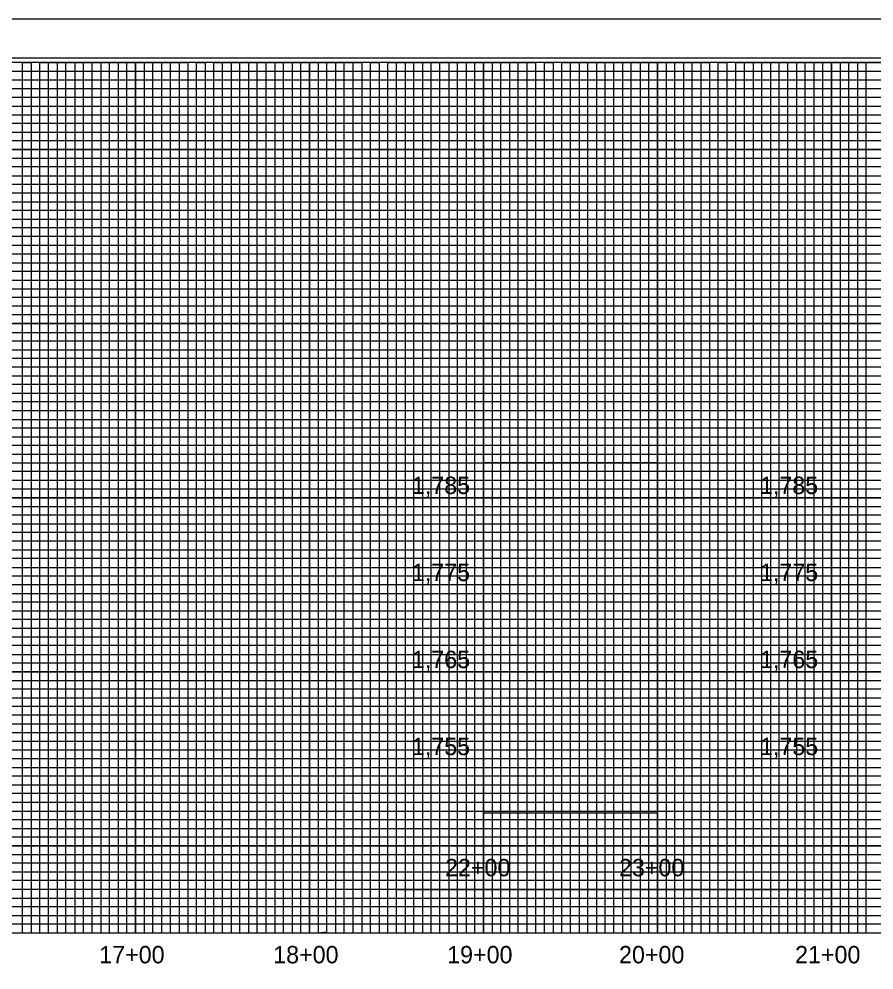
# Model space of a CAD drawing. Extents: x 505692 to 507376, y 438761 to 439861.
# Drawn here: x 506542 to 507033, y 439315 to 439861 of the extents above; entities that cross this region are included whole.
import ezdxf

# ---------------------------------------------------------------- set-up
doc = ezdxf.new("R2010")
doc.units = 0
for name, color, linetype in [('Exist Vertical Profile Vertical Axis Label', 7, 'Continuous'), ('Prop Grid Mask', 7, 'Continuous'), ('Sheet Cutting Line CELL', 7, 'Continuous'), ('Sheet DOT Grid CELL', 7, 'Continuous'), ('Sheet Layout Profile Border Port 1', 7, 'Continuous'), ('Sheet Plot Border Inside CELL', 7, 'Continuous'), ('Sheet Plot Border Outside CELL', 7, 'Continuous'), ('Sheet Profile CELL', 7, 'Continuous'), ('Sheet Profile Grid Major CELL', 7, 'Continuous'), ('Sheet Profile Grid Middle CELL', 7, 'Continuous'), ('Sheet Profile Grid Minor CELL', 7, 'Continuous')]:
    doc.layers.add(name, color=color, linetype=linetype)

msp = doc.modelspace()

# ---------------------------------------------------------------- linework, layer by layer
at = {"layer": 'Prop Grid Mask'}
msp.add_lwpolyline([(506758.68, 439386.14), (507008.68, 439386.14), (507008.68, 439361.14), (506758.68, 439361.14)], close=True, dxfattribs=at)
at = {"layer": 'Sheet Cutting Line CELL'}
msp.add_line((507375.68, 439861.14), (505691.68, 439861.14), dxfattribs=at)
at = {"layer": 'Sheet DOT Grid CELL'}
for p, q in [((506558.68, 439336.14), (506558.68, 439836.14)), ((506608.68, 439336.14), (506608.68, 439836.14)), ((506658.68, 439336.14), (506658.68, 439836.14)), ((506708.68, 439336.14), (506708.68, 439836.14)), ((506758.68, 439336.14), (506758.68, 439836.14)), ((506808.68, 439336.14), (506808.68, 439836.14)), ((506858.68, 439336.14), (506858.68, 439836.14)), ((506908.68, 439336.14), (506908.68, 439836.14)), ((506958.68, 439336.14), (506958.68, 439836.14)), ((507008.68, 439336.14), (507008.68, 439836.14)), ((507158.63, 439786.14), (505858.68, 439786.14)), ((507158.63, 439736.14), (505858.68, 439736.14)), ((507158.68, 439686.14), (505858.68, 439686.14)), ((507358.68, 439636.14), (505858.68, 439636.14)), ((507358.68, 439586.14), (505858.68, 439586.14)), ((507358.68, 439536.14), (505858.68, 439536.14)), ((507358.68, 439486.14), (505858.68, 439486.14)), ((507358.68, 439436.14), (505858.68, 439436.14)), ((507358.68, 439386.14), (505858.68, 439386.14))]:
    msp.add_line(p, q, dxfattribs=at)
at = {"layer": 'Sheet Layout Profile Border Port 1'}
for points in [[(505908.68, 439836.14), (505908.68, 439336.14), (507108.68, 439336.14), (507108.68, 439486.14), (507108.68, 439636.14), (507108.68, 439836.14)], [(506808.68, 439405.04), (506908.68, 439405.04), (506908.68, 439606.14), (506808.68, 439606.14)]]:
    msp.add_lwpolyline(points, close=True, dxfattribs=at)
at = {"layer": 'Sheet Plot Border Inside CELL'}
msp.add_lwpolyline([(505704.68, 438783.59), (507371.18, 438783.59), (507371.18, 439838.69), (505704.68, 439838.69)], close=True, dxfattribs=at)
at = {"layer": 'Sheet Plot Border Outside CELL'}
msp.add_lwpolyline([(505691.68, 438761.14), (507375.68, 438761.14), (507375.68, 439861.14), (505691.68, 439861.14)], close=True, dxfattribs=at)
at = {"layer": 'Sheet Profile CELL'}
for p, q in [((506758.68, 439361.14), (506758.68, 439611.14)), ((506758.68, 439611.14), (507008.68, 439611.14)), ((506808.68, 439386.14), (506808.68, 439611.14)), ((506958.68, 439386.14), (506958.68, 439611.14)), ((507008.68, 439361.14), (507008.68, 439611.14)), ((506758.68, 439386.14), (507008.68, 439386.14)), ((506758.68, 439361.14), (507008.68, 439361.14)), ((505858.68, 439336.14), (507358.68, 439336.14))]:
    msp.add_line(p, q, dxfattribs=at)
msp.add_lwpolyline([(507358.68, 439836.14), (505858.68, 439836.14), (505858.68, 438786.14), (507358.68, 438786.14)], close=True, dxfattribs=at)
at = {"layer": 'Sheet Profile Grid Major CELL'}
for points in [[(506508.68, 439336.14), (506558.68, 439336.14), (506558.68, 439836.14), (506608.68, 439836.14), (506608.68, 439336.14), (506658.68, 439336.14), (506658.68, 439836.14), (506708.68, 439836.14), (506708.68, 439336.14), (506758.68, 439336.14), (506758.68, 439836.14), (506808.68, 439836.14), (506808.68, 439336.14), (506858.68, 439336.14), (506858.68, 439836.14), (506908.68, 439836.14), (506908.68, 439336.14), (506958.68, 439336.14), (506958.68, 439836.14), (507008.68, 439836.14), (507008.68, 439336.14), (507058.68, 439336.14)], [(505858.68, 439786.14), (507158.68, 439786.14)], [(507158.68, 439736.14), (505858.68, 439736.14), (505858.68, 439686.14), (507158.68, 439686.14)], [(507358.68, 439636.14), (505858.68, 439636.14), (505858.68, 439586.14), (507358.68, 439586.14)], [(507358.68, 439536.14), (505858.68, 439536.14), (505858.68, 439486.14), (507358.68, 439486.14)], [(507358.68, 439436.14), (505858.68, 439436.14), (505858.68, 439436.14), (505858.68, 439386.14), (507358.68, 439386.14)]]:
    msp.add_lwpolyline(points, dxfattribs=at)
at = {"layer": 'Sheet Profile Grid Middle CELL'}
msp.add_line((505858.68, 439811.14), (507158.63, 439811.14), dxfattribs=at)
for points in [[(506533.68, 439336.14), (506583.68, 439336.14), (506583.68, 439836.14), (506633.68, 439836.14), (506633.68, 439336.14), (506683.68, 439336.14), (506683.68, 439836.14), (506733.68, 439836.14), (506733.68, 439336.14), (506783.68, 439336.14), (506783.68, 439836.14), (506833.68, 439836.14), (506833.68, 439336.14), (506883.68, 439336.14), (506883.68, 439836.14), (506933.68, 439836.14), (506933.68, 439336.14), (506983.68, 439336.14), (506983.68, 439836.14), (507033.68, 439836.14)], [(507158.68, 439761.14), (505858.68, 439761.14), (505858.68, 439711.14), (507158.68, 439711.14)], [(507358.68, 439661.14), (505858.68, 439661.14), (505858.68, 439611.14), (507183.68, 439611.14)], [(507358.68, 439561.14), (505858.68, 439561.14), (505858.68, 439511.14), (507358.68, 439511.14)], [(507358.68, 439461.14), (505858.68, 439461.14), (505858.68, 439411.14), (507358.68, 439411.14)], [(507358.68, 439361.14), (505858.68, 439361.14)]]:
    msp.add_lwpolyline(points, dxfattribs=at)
at = {"layer": 'Sheet Profile Grid Minor CELL'}
for p, q in [((505908.68, 439831.14), (507158.68, 439831.14)), ((507158.68, 439826.14), (505908.68, 439825.79)), ((505908.68, 439821.14), (507158.68, 439821.14)), ((507158.63, 439701.14), (505908.68, 439701.14)), ((507158.68, 439696.14), (505908.68, 439696.14)), ((507158.68, 439691.14), (505908.68, 439691.14)), ((505908.68, 439681.14), (507158.68, 439681.14)), ((507158.68, 439676.14), (505908.68, 439676.14)), ((505908.68, 439671.14), (507308.68, 439671.14)), ((507308.68, 439651.14), (505908.68, 439651.14)), ((505908.68, 439646.14), (507308.68, 439646.14)), ((507308.68, 439626.14), (505908.68, 439626.14)), ((505908.68, 439621.14), (507308.68, 439621.14)), ((507308.68, 439601.14), (505908.68, 439601.14)), ((505908.68, 439596.14), (507308.68, 439596.14)), ((507308.68, 439591.14), (505908.68, 439591.14)), ((505908.68, 439581.14), (507308.68, 439581.14)), ((507308.68, 439576.14), (505908.68, 439576.14)), ((505908.68, 439571.14), (507308.68, 439571.14)), ((507308.68, 439566.14), (505908.68, 439566.14)), ((505908.68, 439556.14), (507308.68, 439556.14)), ((507308.68, 439551.14), (505908.68, 439551.14)), ((505908.68, 439546.14), (507308.68, 439546.14)), ((507308.68, 439541.14), (505908.68, 439541.14)), ((505908.68, 439531.14), (507308.68, 439531.14)), ((507308.68, 439526.14), (505908.68, 439526.14)), ((505908.68, 439521.14), (507308.68, 439521.14)), ((507308.68, 439516.14), (505908.68, 439516.14)), ((505908.68, 439506.14), (507308.68, 439506.14)), ((507308.68, 439501.14), (505908.68, 439501.14)), ((505908.68, 439496.14), (507308.68, 439496.14)), ((507308.68, 439491.14), (505908.68, 439491.14)), ((505908.68, 439481.14), (507308.68, 439481.14)), ((507308.68, 439476.14), (505908.68, 439476.14)), ((505908.68, 439471.14), (507308.68, 439471.14)), ((507308.68, 439466.14), (505908.68, 439466.14)), ((505908.68, 439456.14), (507308.68, 439456.14)), ((507308.68, 439451.14), (505908.68, 439451.14)), ((507308.68, 439446.14), (505908.68, 439446.14)), ((507308.68, 439441.14), (505908.68, 439441.14)), ((505908.68, 439431.14), (507308.68, 439431.14)), ((507308.68, 439426.14), (505908.68, 439426.14)), ((505908.68, 439421.14), (507308.68, 439421.14)), ((507308.68, 439416.14), (505908.68, 439416.14)), ((505908.68, 439406.14), (507308.68, 439406.14)), ((507308.68, 439401.14), (505908.68, 439401.14)), ((505908.68, 439396.14), (507308.68, 439396.14)), ((507308.68, 439391.14), (505908.68, 439391.14)), ((505908.68, 439381.14), (507308.68, 439381.14)), ((507308.68, 439376.14), (505908.68, 439376.14)), ((505908.68, 439371.14), (507308.68, 439371.14)), ((507308.68, 439366.14), (505908.68, 439366.14)), ((505908.68, 439356.14), (507308.68, 439356.14)), ((507308.68, 439351.14), (505908.68, 439351.14)), ((505908.68, 439346.14), (507308.68, 439346.14))]:
    msp.add_line(p, q, dxfattribs=at)
for points in [[(506538.68, 439336.14), (506543.68, 439336.14), (506543.68, 439836.14), (506548.68, 439836.14), (506548.68, 439336.14), (506553.68, 439336.14), (506553.68, 439836.14), (506563.68, 439836.14), (506563.68, 439336.14), (506563.68, 439336.14), (506568.68, 439336.14), (506568.68, 439836.14), (506573.68, 439836.14), (506573.68, 439336.14), (506578.68, 439336.14), (506578.68, 439836.14), (506588.68, 439836.14), (506588.68, 439336.14), (506593.68, 439336.14), (506593.68, 439836.14), (506598.68, 439836.14), (506598.68, 439336.14), (506603.68, 439336.14), (506603.68, 439836.14), (506613.68, 439836.14), (506613.68, 439336.14), (506618.68, 439336.14), (506618.68, 439836.14), (506623.68, 439836.14), (506623.68, 439336.14), (506628.68, 439336.14), (506628.68, 439836.14), (506638.68, 439836.14), (506638.68, 439336.14), (506643.68, 439336.14), (506643.68, 439836.14), (506648.68, 439836.14), (506648.68, 439336.14), (506653.68, 439336.14), (506653.68, 439836.14), (506663.68, 439836.14), (506663.68, 439336.14), (506668.68, 439336.14), (506668.68, 439836.14), (506673.68, 439836.14), (506673.68, 439336.14), (506678.68, 439336.14), (506678.68, 439836.14), (506688.68, 439836.14), (506688.68, 439336.14), (506693.68, 439336.14), (506693.68, 439836.14), (506698.68, 439836.14), (506698.68, 439336.14), (506703.68, 439336.14), (506703.68, 439836.14), (506713.68, 439836.14), (506713.68, 439336.14), (506718.38, 439336.69), (506718.68, 439336.14), (506718.68, 439836.14), (506723.68, 439836.14), (506723.68, 439336.14), (506728.68, 439336.14), (506728.68, 439836.14), (506738.68, 439836.14), (506738.68, 439336.14), (506743.68, 439336.14)], [(506743.68, 439336.14), (506743.68, 439836.14), (506748.68, 439836.14), (506748.68, 439336.14), (506753.68, 439336.14), (506753.68, 439836.14), (506763.68, 439836.14), (506763.68, 439336.14), (506768.68, 439336.14), (506768.68, 439836.14), (506773.68, 439836.14), (506773.68, 439336.14), (506778.68, 439336.14), (506778.68, 439836.14), (506788.68, 439836.14), (506788.68, 439336.14), (506793.68, 439336.14), (506793.68, 439836.14), (506798.68, 439836.14), (506798.68, 439336.14), (506803.68, 439336.14), (506803.68, 439836.14), (506813.68, 439836.14), (506813.68, 439336.14), (506818.68, 439336.14), (506818.68, 439836.14), (506823.68, 439836.14), (506823.68, 439336.14), (506828.68, 439336.14), (506828.68, 439836.14), (506838.68, 439836.14), (506838.68, 439336.14), (506843.68, 439336.14), (506843.68, 439836.14), (506848.68, 439836.14), (506848.68, 439336.14), (506853.68, 439336.14), (506853.68, 439836.14), (506863.68, 439836.14), (506863.68, 439336.14), (506868.68, 439336.14), (506868.68, 439836.14), (506873.68, 439836.14), (506873.68, 439336.14), (506878.68, 439336.14), (506878.68, 439836.14), (506888.68, 439836.14), (506888.68, 439336.14), (506893.68, 439336.14), (506893.68, 439836.14), (506898.68, 439836.14), (506898.68, 439336.14), (506903.68, 439336.14), (506903.68, 439836.14), (506913.68, 439836.14), (506913.68, 439336.14), (506918.68, 439336.14), (506918.68, 439836.14), (506923.68, 439836.14), (506923.68, 439336.14), (506928.68, 439336.14), (506928.68, 439836.14), (506938.68, 439836.14), (506938.68, 439336.14), (506943.68, 439336.14), (506943.68, 439836.14), (506948.68, 439836.14), (506948.68, 439336.14), (506953.68, 439336.14), (506953.68, 439836.14), (506963.68, 439836.14), (506963.68, 439336.14), (506968.68, 439336.14), (506968.68, 439836.14), (506973.68, 439836.14), (506973.68, 439336.14), (506978.68, 439336.14), (506978.68, 439836.14), (506988.68, 439836.14), (506988.68, 439336.14), (506993.68, 439336.14), (506993.68, 439836.14), (506998.68, 439836.14), (506998.68, 439336.14), (507003.68, 439336.14), (507003.68, 439836.14), (507013.68, 439836.14), (507013.68, 439336.14), (507018.68, 439336.14), (507018.68, 439836.14), (507023.68, 439836.14), (507023.68, 439336.14), (507028.68, 439336.14), (507028.68, 439836.14), (507038.68, 439836.14)], [(507158.68, 439816.14), (505908.68, 439816.14), (505908.68, 439806.14), (507158.68, 439806.14)], [(507158.63, 439801.14), (505908.68, 439801.14), (505908.68, 439796.14), (507158.68, 439796.14)], [(507158.68, 439791.14), (505908.68, 439791.14), (505908.68, 439781.14), (507158.68, 439781.14)], [(507158.68, 439776.14), (505908.68, 439776.14), (505908.68, 439771.14), (507158.68, 439771.14)], [(507158.68, 439766.14), (505908.68, 439766.14), (505908.68, 439756.14), (507158.68, 439756.14)], [(507158.68, 439751.14), (505908.68, 439751.14), (505908.68, 439746.14), (507158.68, 439746.14)], [(507158.68, 439741.14), (505908.68, 439741.14), (505908.68, 439731.14), (507158.68, 439731.14)], [(507158.68, 439726.04), (505908.78, 439726.04), (505908.78, 439721.14), (507158.68, 439721.14)], [(507158.68, 439716.14), (505908.68, 439716.14), (505908.68, 439706.14), (507158.68, 439706.14)], [(507308.68, 439666.14), (505908.68, 439666.14), (505908.68, 439656.14), (507308.68, 439656.14)], [(507308.68, 439641.14), (505908.68, 439641.14), (505908.68, 439631.14), (507308.68, 439631.14)], [(507308.68, 439616.14), (505908.68, 439616.14), (505908.68, 439606.14), (507308.68, 439606.14)], [(507308.68, 439341.14), (505908.68, 439341.14)]]:
    msp.add_lwpolyline(points, dxfattribs=at)

# ---------------------------------------------------------------- texts
at = {"layer": 'Exist Vertical Profile Vertical Axis Label'}
for s, p in [('1,785', (506767.53, 439588.24)), ('1,785', (506967.65, 439588.24)), ('1,775', (506767.53, 439538.24)), ('1,775', (506967.65, 439538.24)), ('1,765', (506767.53, 439488.24)), ('1,765', (506967.65, 439488.24)), ('1,755', (506767.53, 439438.24)), ('1,755', (506967.65, 439438.24)), ('22+00', (506786.61, 439368.64)), ('23+00', (506886.61, 439368.64)), ('17+00', (506587.81, 439318.64)), ('18+00', (506687.81, 439318.64)), ('19+00', (506787.81, 439318.64)), ('20+00', (506886.61, 439318.64)), ('21+00', (506987.81, 439318.64))]:
    msp.add_text(s, height=10, dxfattribs=at).set_placement(p)

doc.saveas('drawing.dxf')
